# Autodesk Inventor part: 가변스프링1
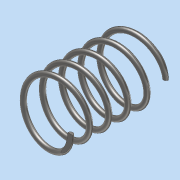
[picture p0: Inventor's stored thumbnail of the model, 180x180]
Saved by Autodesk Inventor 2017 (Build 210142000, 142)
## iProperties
Part Number: 가변스프링1
Material: 강철, 연강
Document SubType Name: Modeling
Designer: MRC
Density: 7.85 g/cm^3
Appearance: 반연마
Mass: 8.42454 g
Surface Area: 21.7273 cm^2
Volume: 1.07319 cm^3
Author: MRC
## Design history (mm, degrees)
sketch "스케치1"
  geometry: L1 (0, 0)-(0, 37.411); L2 (0, 0)-(11, 0); L3 (0, 37.411)-(11, 37.411); C1 r 1 at (11, 0)
  constraints: 6 end point, 2 horizontal, 1 centre point, 1 coincident, 1 vertical
  dimensions: "d0" = 11 distance of L1.start L2.end; "d1" = 11 distance of L1.end L3.end; "d2" = 2 diameter of C1; "d3" = 37.4112 distance of L1.start L1.end (derived)
feature "코일1" sketch "스케치1" pitch "d4" = 10; turns "d6" = 5; dims "d5" = 37.4112 (= d3), "d7" = 0, angle "d8" = 90 deg, angle "d9" = 90 deg, "d10" = 0, "d11" = 0
sketch "스케치2"
  geometry: L1 (37.411, 20)-(0, 20); L2 (0, 20)-(0, -20); L3 (0, -20)-(37.411, -20); L4 (37.411, -20)-(37.411, 20); 2 further points
  constraints: 8 end point, 2 parallel, 1 coincident, 1 horizontal, 1 midpoint, 1 perpendicular
  dimensions: "d13" = 37.4112 distance of L2.end L3.end (= d3); "d14" = 40 distance of L3.end L1.start
extrude "돌출1" sketch "스케치2" stored distance "d15" = 0; taper "d16" = 0 deg
node "솔리드1"
